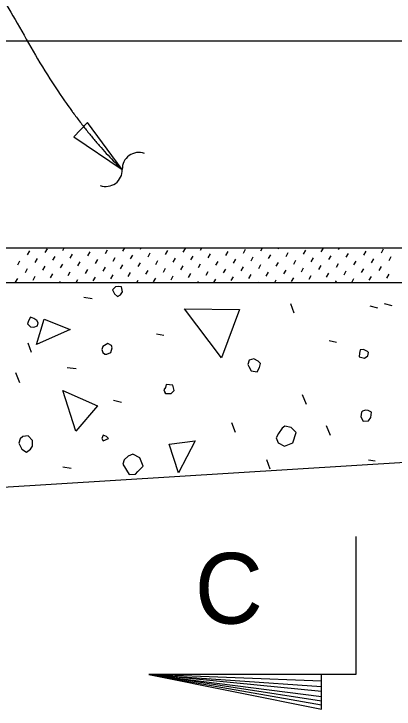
# Model space of a CAD drawing. Extents: x 1.5 to 68.7, y 0 to 31.
# Drawn here: x 28.879 to 30.257, y 10.263 to 12.779 of the extents above; entities that cross this region are included whole.
import ezdxf

# ---------------------------------------------------------------- set-up
doc = ezdxf.new("R2010")
doc.units = 0
for name, color, linetype in [('AdhocPoint_dp', 7, 'Continuous'), ('Patterning', 7, 'Continuous'), ('PlotBorder_dp', 7, 'Continuous'), ('TextMisc', 7, 'Continuous')]:
    doc.layers.add(name, color=color, linetype=linetype)

msp = doc.modelspace()

# ---------------------------------------------------------------- linework, layer by layer
at = {"layer": 'AdhocPoint_dp'}
for p, q in [((29.9931, 10.3647), (29.3681, 10.3881)), ((29.3681, 10.3881), (29.9931, 10.3447)), ((29.9931, 10.3264), (29.3681, 10.3881)), ((29.3681, 10.3881), (29.9931, 10.3081)), ((29.9931, 10.2914), (29.3681, 10.3881)), ((29.3681, 10.3881), (29.9931, 10.2781))]:
    msp.add_line(p, q, dxfattribs=at)
msp.add_lwpolyline([(29.2714, 12.2154), (29.1461, 12.3855), (29.0971, 12.3347)], close=True, dxfattribs=at)
msp.add_lwpolyline([(30.1181, 10.8881), (30.1181, 10.3881), (29.3681, 10.3881), (29.9931, 10.2631), (29.9931, 10.3881)], dxfattribs=at)
for centre, start, end in [((29.3316, 12.2178), 70.0924, 181.8197), ((29.2124, 12.214), 250.0924, 1.8197)]:
    msp.add_arc(centre, 0.0596, start, end, dxfattribs=at)
msp.add_open_spline([(28.4708, 12.9203), (28.7034, 12.864), (28.7449, 13.0099), (29.089, 12.3912), (29.2714, 12.2154)], degree=2, dxfattribs=at)
at = {"layer": 'Patterning'}
for p, q in [((28.9926, 11.9151), (29.0007, 11.9291)), ((29.0561, 11.9232), (29.0612, 11.932)), ((29.1196, 11.9313), (29.12, 11.932)), ((29.2107, 11.9117), (29.2188, 11.9257)), ((29.2742, 11.9198), (29.2813, 11.932)), ((29.3377, 11.9279), (29.3401, 11.932)), ((29.4924, 11.9164), (29.5005, 11.9304)), ((29.5559, 11.9245), (29.5602, 11.932)), ((29.7106, 11.913), (29.7187, 11.927)), ((29.7741, 11.9211), (29.7804, 11.932)), ((29.8376, 11.9292), (29.8392, 11.932)), ((29.9922, 11.9177), (30.0003, 11.9317)), ((30.0557, 11.9258), (30.0593, 11.932)), ((30.2104, 11.9143), (30.2185, 11.9283)), ((28.9291, 11.907), (28.9372, 11.921)), ((29.0203, 11.8874), (29.0284, 11.9014)), ((29.0838, 11.8955), (29.0919, 11.9095)), ((29.1473, 11.9036), (29.1554, 11.9176)), ((29.3019, 11.8921), (29.31, 11.9061)), ((29.3654, 11.9002), (29.3735, 11.9142)), ((29.4289, 11.9083), (29.437, 11.9223)), ((29.5201, 11.8887), (29.5282, 11.9027)), ((29.5836, 11.8968), (29.5917, 11.9108)), ((29.6471, 11.9049), (29.6552, 11.9189)), ((29.8018, 11.8934), (29.8099, 11.9074)), ((29.8653, 11.9015), (29.8734, 11.9155)), ((29.9288, 11.9096), (29.9369, 11.9236)), ((30.0199, 11.89), (30.028, 11.904)), ((30.0834, 11.8981), (30.0915, 11.9121)), ((30.1469, 11.9062), (30.155, 11.9202)), ((30.2381, 11.8867), (30.2462, 11.9006)), ((28.8933, 11.8712), (28.9014, 11.8852)), ((28.9568, 11.8793), (28.9649, 11.8933)), ((29.1115, 11.8678), (29.1196, 11.8818)), ((29.1749, 11.8759), (29.1831, 11.8899)), ((29.2384, 11.884), (29.2465, 11.898)), ((29.3296, 11.8644), (29.3377, 11.8784)), ((29.3931, 11.8725), (29.4012, 11.8865)), ((29.4566, 11.8806), (29.4647, 11.8946)), ((29.6113, 11.8691), (29.6194, 11.8831)), ((29.6748, 11.8772), (29.6829, 11.8912)), ((29.7383, 11.8853), (29.7464, 11.8993)), ((29.8295, 11.8657), (29.8376, 11.8797)), ((29.893, 11.8738), (29.9011, 11.8878)), ((29.9564, 11.8819), (29.9646, 11.8959)), ((30.0476, 11.8623), (30.0557, 11.8763)), ((30.1111, 11.8704), (30.1192, 11.8844)), ((30.1746, 11.8785), (30.1827, 11.8925)), ((28.921, 11.8435), (28.9291, 11.8575)), ((28.9845, 11.8516), (28.9926, 11.8656)), ((29.048, 11.8597), (29.0561, 11.8737)), ((29.1392, 11.8401), (29.1473, 11.8541)), ((29.2026, 11.8482), (29.2107, 11.8622)), ((29.2661, 11.8563), (29.2742, 11.8703)), ((29.3573, 11.8367), (29.3654, 11.8507)), ((29.4208, 11.8448), (29.4289, 11.8588)), ((29.4843, 11.8529), (29.4924, 11.8669)), ((29.5478, 11.861), (29.5559, 11.875)), ((29.639, 11.8414), (29.6471, 11.8554)), ((29.7025, 11.8495), (29.7106, 11.8635)), ((29.766, 11.8576), (29.7741, 11.8716)), ((29.8572, 11.838), (29.8653, 11.852)), ((29.9207, 11.8461), (29.9288, 11.8601)), ((29.9841, 11.8542), (29.9922, 11.8682)), ((30.1388, 11.8428), (30.1469, 11.8567)), ((30.2023, 11.8509), (30.2104, 11.8648)), ((28.9487, 11.8158), (28.9568, 11.8298)), ((29.0122, 11.8239), (29.0203, 11.8379)), ((29.0757, 11.832), (29.0838, 11.846)), ((29.1668, 11.8124), (29.1749, 11.8264)), ((29.2303, 11.8205), (29.2384, 11.8345)), ((29.2938, 11.8286), (29.3019, 11.8426)), ((29.4485, 11.8171), (29.4566, 11.8311)), ((29.512, 11.8252), (29.5201, 11.8392)), ((29.5755, 11.8333), (29.5836, 11.8473)), ((29.6667, 11.8137), (29.6748, 11.8277)), ((29.7302, 11.8218), (29.7383, 11.8358)), ((29.7937, 11.8299), (29.8018, 11.8439)), ((29.9483, 11.8184), (29.9564, 11.8324)), ((30.0118, 11.8265), (30.0199, 11.8405)), ((30.0753, 11.8346), (30.0834, 11.8486)), ((30.1665, 11.8151), (30.1746, 11.8291)), ((30.23, 11.8232), (30.2381, 11.8372)), ((28.8852, 11.8077), (28.8933, 11.8217)), ((29.0461, 11.807), (29.048, 11.8102)), ((29.1049, 11.807), (29.1115, 11.8183)), ((29.325, 11.807), (29.3296, 11.8149)), ((29.385, 11.809), (29.3931, 11.823)), ((29.5452, 11.807), (29.5478, 11.8115)), ((29.604, 11.807), (29.6113, 11.8196)), ((29.7653, 11.807), (29.766, 11.8081)), ((29.8241, 11.807), (29.8295, 11.8162)), ((29.8849, 11.8103), (29.893, 11.8243)), ((30.0442, 11.807), (30.0476, 11.8128)), ((30.103, 11.807), (30.1111, 11.8209)), ((29.1327, 11.7539), (29.1628, 11.7486)), ((29.8947, 11.6956), (29.8823, 11.7292)), ((30.2204, 11.7314), (30.2486, 11.7243)), ((30.1687, 11.7221), (30.1969, 11.7151)), ((29.3961, 11.6214), (29.4227, 11.6161)), ((28.9432, 11.5537), (28.9308, 11.5873)), ((30.0219, 11.5966), (30.0484, 11.5913)), ((29.0726, 11.4994), (29.1045, 11.4959)), ((28.9007, 11.4441), (28.8866, 11.4795)), ((29.9388, 11.365), (29.9247, 11.4004)), ((29.2406, 11.3809), (29.2689, 11.3739)), ((29.6825, 11.2643), (29.6684, 11.2996)), ((30.0259, 11.2532), (30.0118, 11.2886)), ((29.808, 11.1317), (29.7957, 11.1653)), ((30.1638, 11.1648), (30.1885, 11.1613)), ((29.0563, 11.1401), (29.0863, 11.1348))]:
    msp.add_line(p, q, dxfattribs=at)
for points in [[(29.2441, 11.7663), (29.2547, 11.7557), (29.2653, 11.7628), (29.2724, 11.7734), (29.2689, 11.7911), (29.26, 11.7928), (29.2477, 11.7911), (29.237, 11.7805), (29.2441, 11.7663)], [(29.6313, 11.5347), (29.4969, 11.7115), (29.6967, 11.7098), (29.6313, 11.5347)], [(28.9396, 11.6466), (28.952, 11.6448), (28.9644, 11.6501), (28.9679, 11.6607), (28.9626, 11.6695), (28.952, 11.6766), (28.9396, 11.6819), (28.9325, 11.6678), (28.929, 11.6572), (28.9396, 11.6466)], [(28.9613, 11.5825), (28.9896, 11.6744), (29.0832, 11.6373), (28.9613, 11.5825)], [(29.2088, 11.5471), (29.2158, 11.5471), (29.23, 11.5542), (29.2353, 11.5701), (29.2335, 11.5789), (29.2194, 11.586), (29.2017, 11.5754), (29.1982, 11.5648), (29.2017, 11.5542), (29.2088, 11.5471)], [(30.1298, 11.5383), (30.1492, 11.533), (30.1616, 11.5418), (30.1634, 11.5542), (30.1598, 11.5577), (30.1457, 11.5648), (30.1333, 11.563), (30.1315, 11.5507), (30.1298, 11.5383)], [(29.7303, 11.5029), (29.7391, 11.487), (29.7603, 11.4835), (29.7691, 11.4994), (29.7727, 11.5135), (29.7638, 11.5224), (29.7479, 11.5312), (29.732, 11.5259), (29.7267, 11.51), (29.7303, 11.5029)], [(29.428, 11.4057), (29.4492, 11.4057), (29.4598, 11.4163), (29.4545, 11.4358), (29.4315, 11.4375), (29.428, 11.4269), (29.4227, 11.4181), (29.428, 11.4057), (29.4244, 11.4092)], [(29.104, 11.2691), (29.0563, 11.4159), (29.1818, 11.3611), (29.104, 11.2691)], [(30.1355, 11.3204), (30.1444, 11.3045), (30.1638, 11.3063), (30.1726, 11.3186), (30.1744, 11.3381), (30.162, 11.3434), (30.1532, 11.3452), (30.1426, 11.3416), (30.139, 11.3381), (30.1355, 11.3204)], [(29.8363, 11.2272), (29.8593, 11.2148), (29.8894, 11.2272), (29.9017, 11.2643), (29.884, 11.282), (29.8611, 11.2873), (29.8505, 11.2802), (29.8381, 11.2607), (29.8292, 11.2448), (29.8363, 11.2272)], [(28.8972, 11.2249), (28.9078, 11.2037), (28.9255, 11.1931), (28.9396, 11.2037), (28.9467, 11.2143), (28.9467, 11.2356), (28.9308, 11.2515), (28.9113, 11.2497), (28.9025, 11.2409), (28.8972, 11.2249)], [(29.203, 11.2338), (29.2225, 11.2426), (29.2154, 11.2497), (29.203, 11.255), (29.1977, 11.2426), (29.203, 11.2338)], [(29.4757, 11.1176), (29.4421, 11.2219), (29.5358, 11.2342), (29.4757, 11.1176)], [(29.2737, 11.1489), (29.2967, 11.1118), (29.3197, 11.1136), (29.3285, 11.1224), (29.348, 11.1419), (29.3356, 11.1719), (29.3108, 11.1861), (29.2932, 11.179), (29.279, 11.1648), (29.2737, 11.1489)]]:
    msp.add_lwpolyline(points, dxfattribs=at)
at = {"layer": 'PlotBorder_dp'}
for p, q in [((25.4726, 12.682), (34.6205, 12.682)), ((25.4726, 11.932), (31.1267, 11.932)), ((27.4727, 11.807), (31.0765, 11.807)), ((26.6926, 10.9319), (30.6926, 11.1819))]:
    msp.add_line(p, q, dxfattribs=at)

# ---------------------------------------------------------------- texts
at = {"layer": 'TextMisc'}
msp.add_text('C', height=0.256, dxfattribs=at).set_placement((29.5344, 10.5723))

doc.saveas('drawing.dxf')
